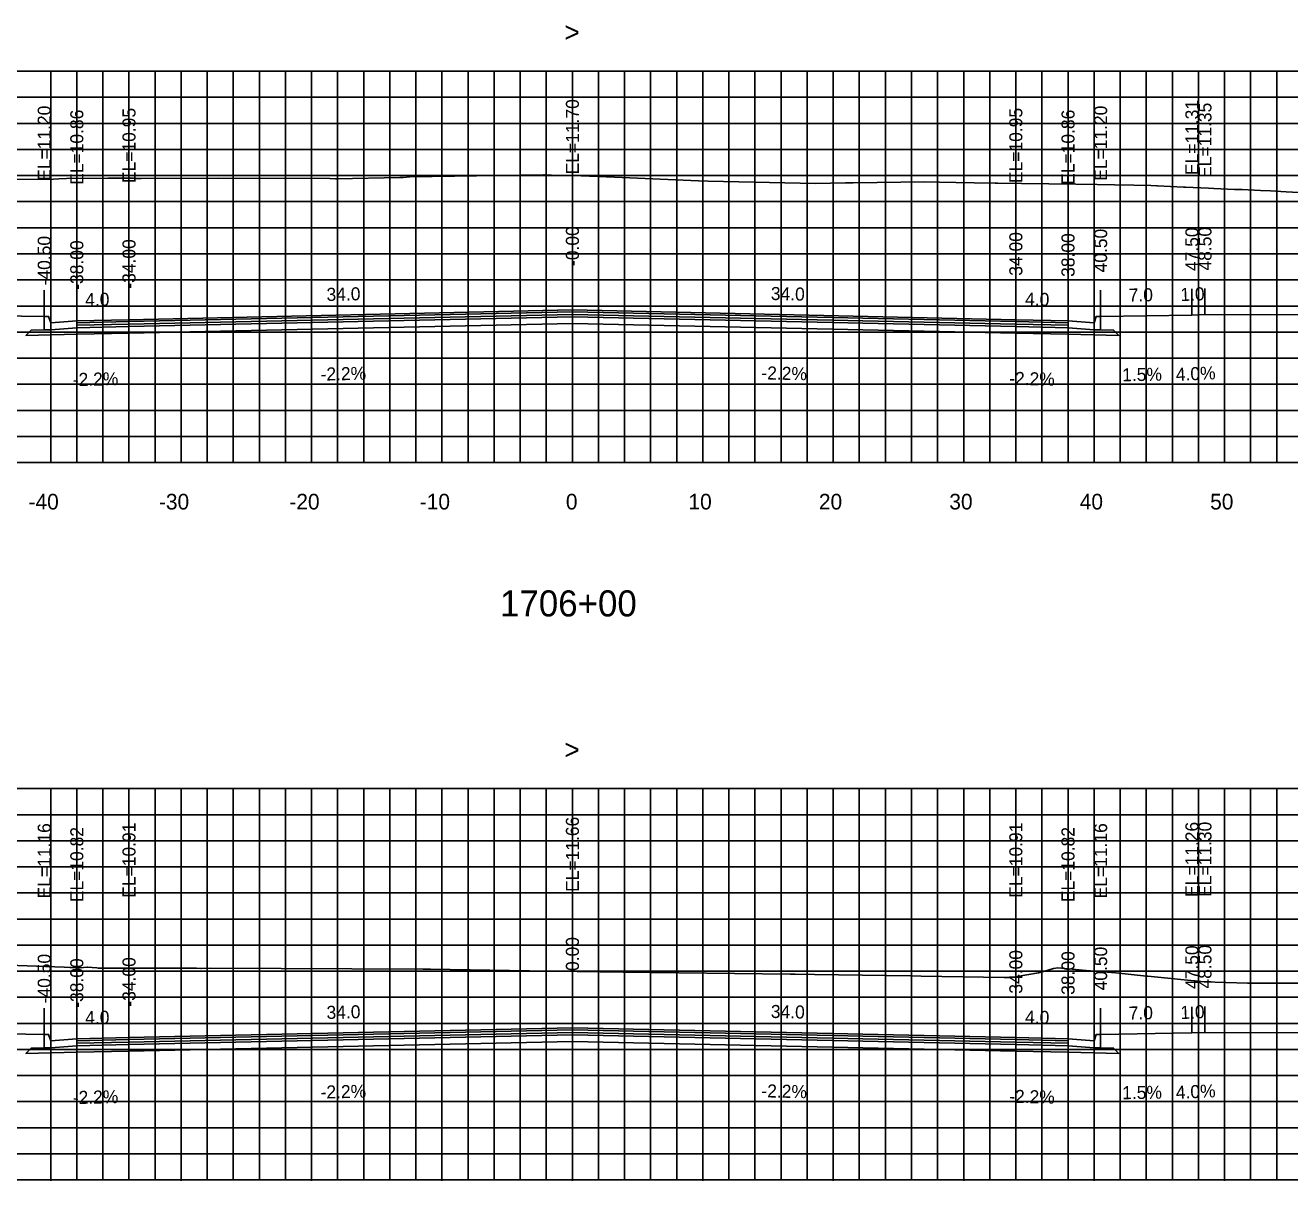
# Model space of a CAD drawing. Extents: x 1797789 to 1803805, y 249066 to 250293.
# Drawn here: x 1802929.1 to 1803026, y 250164.4 to 250253 of the extents above; entities that cross this region are included whole.
import ezdxf

# ---------------------------------------------------------------- set-up
doc = ezdxf.new("R2010")
doc.units = 0
for name, color, linetype in [('1', 7, 'Continuous'), ('10', 7, 'Continuous'), ('3', 7, 'Continuous'), ('4', 7, 'Continuous'), ('60', 7, 'Continuous'), ('BASE', 7, 'Continuous'), ('CL-CNST', 7, 'Continuous'), ('Level 62', 7, 'Continuous'), ('LOWER BINDER', 7, 'Continuous'), ('M-ROADS', 7, 'Continuous'), ('UPPER BINDER', 7, 'Continuous'), ('WEARING', 7, 'Continuous')]:
    doc.layers.add(name, color=color, linetype=linetype)

msp = doc.modelspace()

# ---------------------------------------------------------------- linework, layer by layer
for p, q in [((1802930.502, 250230.635), (1802930.502, 250232.635)), ((1802930.505, 250230.635), (1802930.505, 250232.635)), ((1802971.002, 250231.131), (1802971.002, 250233.131)), ((1803011.498, 250230.635), (1803011.498, 250232.635)), ((1803011.502, 250230.635), (1803011.502, 250232.635)), ((1803018.502, 250230.74), (1803018.502, 250232.74)), ((1803019.502, 250230.78), (1803019.502, 250232.78)), ((1802933.002, 250230.295), (1802933.002, 250232.295)), ((1802937.002, 250230.383), (1802937.002, 250232.383)), ((1803005.002, 250230.383), (1803005.002, 250232.383)), ((1803009.002, 250230.295), (1803009.002, 250232.295)), ((1802930.502, 250175.592), (1802930.502, 250177.592)), ((1802930.505, 250175.591), (1802930.505, 250177.591)), ((1802933.002, 250175.251), (1802933.002, 250177.251)), ((1802937.002, 250175.339), (1802937.002, 250177.339)), ((1802971.002, 250176.087), (1802971.002, 250178.087)), ((1803005.002, 250175.339), (1803005.002, 250177.339)), ((1803009.002, 250175.251), (1803009.002, 250177.251)), ((1803011.498, 250175.591), (1803011.498, 250177.591)), ((1803011.502, 250175.592), (1803011.502, 250177.592)), ((1803018.502, 250175.697), (1803018.502, 250177.697)), ((1803019.502, 250175.737), (1803019.502, 250177.737))]:
    msp.add_line(p, q)
for points in [[(1802933.002, 250230.295), (1802931.002, 250230.135), (1802930.835, 250230.635), (1802930.505, 250230.635), (1802930.505, 250229.605), (1802931.002, 250229.605), (1802933.002, 250229.765)], [(1803009.002, 250230.295), (1803011.002, 250230.135), (1803011.168, 250230.635), (1803011.498, 250230.635), (1803011.498, 250229.605), (1803011.002, 250229.605), (1803009.002, 250229.765)], [(1802933.002, 250175.251), (1802931.002, 250175.091), (1802930.835, 250175.591), (1802930.505, 250175.591), (1802930.505, 250174.561), (1802931.002, 250174.561), (1802933.002, 250174.721)], [(1803009.002, 250175.251), (1803011.002, 250175.091), (1803011.168, 250175.591), (1803011.498, 250175.591), (1803011.498, 250174.561), (1803011.002, 250174.561), (1803009.002, 250174.721)]]:
    msp.add_lwpolyline(points, close=True)
at = {"layer": '60'}
for p, q in [((1802821.002, 250219.432), (1803121.002, 250219.432)), ((1802931.002, 250219.372), (1802931.002, 250219.432)), ((1802941.002, 250219.372), (1802941.002, 250219.432)), ((1802951.002, 250219.372), (1802951.002, 250219.432)), ((1802961.002, 250219.372), (1802961.002, 250219.432)), ((1802971.002, 250219.372), (1802971.002, 250219.432)), ((1802981.002, 250219.372), (1802981.002, 250219.432)), ((1802991.002, 250219.372), (1802991.002, 250219.432)), ((1803001.002, 250219.372), (1803001.002, 250219.432)), ((1803011.002, 250219.372), (1803011.002, 250219.432)), ((1803021.002, 250219.372), (1803021.002, 250219.432)), ((1802821.002, 250164.432), (1803121.002, 250164.432)), ((1802931.002, 250164.372), (1802931.002, 250164.432)), ((1802941.002, 250164.372), (1802941.002, 250164.432)), ((1802951.002, 250164.372), (1802951.002, 250164.432)), ((1802961.002, 250164.372), (1802961.002, 250164.432)), ((1802971.002, 250164.372), (1802971.002, 250164.432)), ((1802981.002, 250164.372), (1802981.002, 250164.432)), ((1802991.002, 250164.372), (1802991.002, 250164.432)), ((1803001.002, 250164.372), (1803001.002, 250164.432)), ((1803011.002, 250164.372), (1803011.002, 250164.432)), ((1803021.002, 250164.372), (1803021.002, 250164.432))]:
    msp.add_line(p, q, dxfattribs=at)
at = {"layer": 'BASE'}
for points in [[(1803009.002, 250229.265), (1803012.902, 250229.179), (1803012.498, 250229.583), (1803011.498, 250229.605), (1803011.002, 250229.605), (1803009.002, 250229.765), (1803005.002, 250229.853), (1802971.002, 250230.601), (1802937.002, 250229.853), (1802933.002, 250229.765), (1802931.002, 250229.605), (1802930.505, 250229.605), (1802929.505, 250229.583), (1802929.101, 250229.179), (1802933.002, 250229.265), (1802937.002, 250229.353), (1802971.002, 250230.101), (1803005.002, 250229.353)], [(1803009.002, 250174.221), (1803012.902, 250174.136), (1803012.498, 250174.539), (1803011.498, 250174.561), (1803011.002, 250174.561), (1803009.002, 250174.721), (1803005.002, 250174.809), (1802971.002, 250175.557), (1802937.002, 250174.809), (1802933.002, 250174.721), (1802931.002, 250174.561), (1802930.505, 250174.561), (1802929.505, 250174.539), (1802929.101, 250174.136), (1802933.002, 250174.221), (1802937.002, 250174.309), (1802971.002, 250175.057), (1803005.002, 250174.309)]]:
    msp.add_lwpolyline(points, close=True, dxfattribs=at)
at = {"layer": 'CL-CNST'}
for points in [[(1802821.002, 250232.81), (1802922.502, 250230.78), (1802923.502, 250230.74), (1802930.502, 250230.635), (1802930.505, 250230.635), (1802930.835, 250230.635), (1802931.002, 250230.135), (1802933.002, 250230.295), (1802937.002, 250230.383), (1802971.002, 250231.131), (1803005.002, 250230.383), (1803009.002, 250230.295), (1803011.002, 250230.135), (1803011.168, 250230.635), (1803011.498, 250230.635), (1803011.502, 250230.635), (1803018.502, 250230.74), (1803019.502, 250230.78), (1803121.002, 250230.709)], [(1802821.002, 250179.096), (1802922.502, 250175.737), (1802923.502, 250175.697), (1802930.502, 250175.592), (1802930.505, 250175.591), (1802930.835, 250175.591), (1802931.002, 250175.091), (1802933.002, 250175.251), (1802937.002, 250175.339), (1802971.002, 250176.087), (1803005.002, 250175.339), (1803009.002, 250175.251), (1803011.002, 250175.091), (1803011.168, 250175.591), (1803011.498, 250175.591), (1803011.502, 250175.592), (1803018.502, 250175.697), (1803019.502, 250175.737), (1803121.002, 250175.671)]]:
    msp.add_lwpolyline(points, dxfattribs=at)
at = {"layer": 'Level 62'}
for p, q in [((1802821.002, 250249.432), (1803121.002, 250249.432)), ((1802931.002, 250219.432), (1802931.002, 250249.432)), ((1802933.002, 250219.432), (1802933.002, 250249.432)), ((1802935.002, 250219.432), (1802935.002, 250249.432)), ((1802937.002, 250219.432), (1802937.002, 250249.432)), ((1802939.002, 250219.432), (1802939.002, 250249.432)), ((1802941.002, 250219.432), (1802941.002, 250249.432)), ((1802943.002, 250219.432), (1802943.002, 250249.432)), ((1802945.002, 250219.432), (1802945.002, 250249.432)), ((1802947.002, 250219.432), (1802947.002, 250249.432)), ((1802949.002, 250219.432), (1802949.002, 250249.432)), ((1802951.002, 250219.432), (1802951.002, 250249.432)), ((1802953.002, 250219.432), (1802953.002, 250249.432)), ((1802955.002, 250219.432), (1802955.002, 250249.432)), ((1802957.002, 250219.432), (1802957.002, 250249.432)), ((1802959.002, 250219.432), (1802959.002, 250249.432)), ((1802961.002, 250219.432), (1802961.002, 250249.432)), ((1802963.002, 250219.432), (1802963.002, 250249.432)), ((1802965.002, 250219.432), (1802965.002, 250249.432)), ((1802967.002, 250219.432), (1802967.002, 250249.432)), ((1802969.002, 250219.432), (1802969.002, 250249.432)), ((1802971.002, 250219.432), (1802971.002, 250249.432)), ((1802973.002, 250219.432), (1802973.002, 250249.432)), ((1802975.002, 250219.432), (1802975.002, 250249.432)), ((1802977.002, 250219.432), (1802977.002, 250249.432)), ((1802979.002, 250219.432), (1802979.002, 250249.432)), ((1802981.002, 250219.432), (1802981.002, 250249.432)), ((1802983.002, 250219.432), (1802983.002, 250249.432)), ((1802985.002, 250219.432), (1802985.002, 250249.432)), ((1802987.002, 250219.432), (1802987.002, 250249.432)), ((1802989.002, 250219.432), (1802989.002, 250249.432)), ((1802991.002, 250219.432), (1802991.002, 250249.432)), ((1802993.002, 250219.432), (1802993.002, 250249.432)), ((1802995.002, 250219.432), (1802995.002, 250249.432)), ((1802997.002, 250219.432), (1802997.002, 250249.432)), ((1802999.002, 250219.432), (1802999.002, 250249.432)), ((1803001.002, 250219.432), (1803001.002, 250249.432)), ((1803003.002, 250219.432), (1803003.002, 250249.432)), ((1803005.002, 250219.432), (1803005.002, 250249.432)), ((1803007.002, 250219.432), (1803007.002, 250249.432)), ((1803009.002, 250219.432), (1803009.002, 250249.432)), ((1803011.002, 250219.432), (1803011.002, 250249.432)), ((1803013.002, 250219.432), (1803013.002, 250249.432)), ((1803015.002, 250219.432), (1803015.002, 250249.432)), ((1803017.002, 250219.432), (1803017.002, 250249.432)), ((1803019.002, 250219.432), (1803019.002, 250249.432)), ((1803021.002, 250219.432), (1803021.002, 250249.432)), ((1803023.002, 250219.432), (1803023.002, 250249.432)), ((1803025.002, 250219.432), (1803025.002, 250249.432)), ((1802821.002, 250247.432), (1803121.002, 250247.432)), ((1802821.002, 250245.432), (1803121.002, 250245.432)), ((1802821.002, 250243.432), (1803121.002, 250243.432)), ((1802821.002, 250241.432), (1803121.002, 250241.432)), ((1802821.002, 250239.432), (1803121.002, 250239.432)), ((1802821.002, 250237.432), (1803121.002, 250237.432)), ((1802821.002, 250235.432), (1803121.002, 250235.432)), ((1802821.002, 250233.432), (1803121.002, 250233.432)), ((1802821.002, 250231.432), (1803121.002, 250231.432)), ((1802821.002, 250229.432), (1803121.002, 250229.432)), ((1802821.002, 250227.432), (1803121.002, 250227.432)), ((1802821.002, 250225.432), (1803121.002, 250225.432)), ((1802821.002, 250223.432), (1803121.002, 250223.432)), ((1802821.002, 250221.432), (1803121.002, 250221.432)), ((1802821.002, 250219.432), (1803121.002, 250219.432)), ((1802821.002, 250194.432), (1803121.002, 250194.432)), ((1802931.002, 250164.432), (1802931.002, 250194.432)), ((1802933.002, 250164.432), (1802933.002, 250194.432)), ((1802935.002, 250164.432), (1802935.002, 250194.432)), ((1802937.002, 250164.432), (1802937.002, 250194.432)), ((1802939.002, 250164.432), (1802939.002, 250194.432)), ((1802941.002, 250164.432), (1802941.002, 250194.432)), ((1802943.002, 250164.432), (1802943.002, 250194.432)), ((1802945.002, 250164.432), (1802945.002, 250194.432)), ((1802947.002, 250164.432), (1802947.002, 250194.432)), ((1802949.002, 250164.432), (1802949.002, 250194.432)), ((1802951.002, 250164.432), (1802951.002, 250194.432)), ((1802953.002, 250164.432), (1802953.002, 250194.432)), ((1802955.002, 250164.432), (1802955.002, 250194.432)), ((1802957.002, 250164.432), (1802957.002, 250194.432)), ((1802959.002, 250164.432), (1802959.002, 250194.432)), ((1802961.002, 250164.432), (1802961.002, 250194.432)), ((1802963.002, 250164.432), (1802963.002, 250194.432)), ((1802965.002, 250164.432), (1802965.002, 250194.432)), ((1802967.002, 250164.432), (1802967.002, 250194.432)), ((1802969.002, 250164.432), (1802969.002, 250194.432)), ((1802971.002, 250164.432), (1802971.002, 250194.432)), ((1802973.002, 250164.432), (1802973.002, 250194.432)), ((1802975.002, 250164.432), (1802975.002, 250194.432)), ((1802977.002, 250164.432), (1802977.002, 250194.432)), ((1802979.002, 250164.432), (1802979.002, 250194.432)), ((1802981.002, 250164.432), (1802981.002, 250194.432)), ((1802983.002, 250164.432), (1802983.002, 250194.432)), ((1802985.002, 250164.432), (1802985.002, 250194.432)), ((1802987.002, 250164.432), (1802987.002, 250194.432)), ((1802989.002, 250164.432), (1802989.002, 250194.432)), ((1802991.002, 250164.432), (1802991.002, 250194.432)), ((1802993.002, 250164.432), (1802993.002, 250194.432)), ((1802995.002, 250164.432), (1802995.002, 250194.432)), ((1802997.002, 250164.432), (1802997.002, 250194.432)), ((1802999.002, 250164.432), (1802999.002, 250194.432)), ((1803001.002, 250164.432), (1803001.002, 250194.432)), ((1803003.002, 250164.432), (1803003.002, 250194.432)), ((1803005.002, 250164.432), (1803005.002, 250194.432)), ((1803007.002, 250164.432), (1803007.002, 250194.432)), ((1803009.002, 250164.432), (1803009.002, 250194.432)), ((1803011.002, 250164.432), (1803011.002, 250194.432)), ((1803013.002, 250164.432), (1803013.002, 250194.432)), ((1803015.002, 250164.432), (1803015.002, 250194.432)), ((1803017.002, 250164.432), (1803017.002, 250194.432)), ((1803019.002, 250164.432), (1803019.002, 250194.432)), ((1803021.002, 250164.432), (1803021.002, 250194.432)), ((1803023.002, 250164.432), (1803023.002, 250194.432)), ((1803025.002, 250164.432), (1803025.002, 250194.432)), ((1802821.002, 250192.432), (1803121.002, 250192.432)), ((1802821.002, 250190.432), (1803121.002, 250190.432)), ((1802821.002, 250188.432), (1803121.002, 250188.432)), ((1802821.002, 250186.432), (1803121.002, 250186.432)), ((1802821.002, 250184.432), (1803121.002, 250184.432)), ((1802821.002, 250182.432), (1803121.002, 250182.432)), ((1802821.002, 250180.432), (1803121.002, 250180.432)), ((1802821.002, 250178.432), (1803121.002, 250178.432)), ((1802821.002, 250176.432), (1803121.002, 250176.432)), ((1802821.002, 250174.432), (1803121.002, 250174.432)), ((1802821.002, 250172.432), (1803121.002, 250172.432)), ((1802821.002, 250170.432), (1803121.002, 250170.432)), ((1802821.002, 250168.432), (1803121.002, 250168.432)), ((1802821.002, 250166.432), (1803121.002, 250166.432)), ((1802821.002, 250164.432), (1803121.002, 250164.432))]:
    msp.add_line(p, q, dxfattribs=at)
at = {"layer": 'LOWER BINDER'}
for points in [[(1802933.002, 250229.765), (1802933.002, 250229.955), (1802937.002, 250230.043), (1802971.002, 250230.791), (1803005.002, 250230.043), (1803009.002, 250229.955), (1803009.002, 250229.765), (1803005.002, 250229.853), (1802971.002, 250230.601), (1802937.002, 250229.853)], [(1802933.002, 250174.721), (1802933.002, 250174.911), (1802937.002, 250174.999), (1802971.002, 250175.747), (1803005.002, 250174.999), (1803009.002, 250174.911), (1803009.002, 250174.721), (1803005.002, 250174.809), (1802971.002, 250175.557), (1802937.002, 250174.809)]]:
    msp.add_lwpolyline(points, close=True, dxfattribs=at)
at = {"layer": 'M-ROADS'}
for points in [[(1802923.411, 250241.142), (1802931.208, 250241.164), (1802931.613, 250241.183), (1802932.202, 250241.21), (1802935.375, 250241.225), (1802937.349, 250241.225), (1802937.466, 250241.219), (1802937.941, 250241.196), (1802943.875, 250241.242), (1802952.391, 250241.207), (1802952.849, 250241.189), (1802952.93, 250241.186), (1802957.764, 250241.279), (1802958.031, 250241.294), (1802958.528, 250241.323), (1802968.795, 250241.483), (1802968.867, 250241.48), (1802969.399, 250241.461), (1802969.967, 250241.433), (1802970.044, 250241.432), (1802970.129, 250241.431), (1802970.685, 250241.437), (1802970.849, 250241.435), (1802971.031, 250241.431), (1802974.229, 250241.316), (1802980.666, 250241.021), (1802981.415, 250241.014), (1802989.634, 250240.82), (1802991.94, 250240.868), (1802992.112, 250240.866), (1802992.525, 250240.863), (1802998.012, 250240.947), (1802999.137, 250240.928), (1803000.394, 250240.908), (1803001.809, 250240.886), (1803003.412, 250240.86), (1803003.61, 250240.862), (1803005.437, 250240.831), (1803007.532, 250240.797), (1803009.614, 250240.768), (1803011.233, 250240.746), (1803012.555, 250240.721), (1803014.053, 250240.692), (1803015.348, 250240.667), (1803015.807, 250240.646), (1803015.849, 250240.644), (1803015.862, 250240.643), (1803017.856, 250240.55), (1803018.02, 250240.544), (1803019.782, 250240.462), (1803020.191, 250240.448), (1803021.767, 250240.376), (1803022.225, 250240.361), (1803022.363, 250240.354), (1803023.751, 250240.292), (1803024.534, 250240.25), (1803025.732, 250240.196), (1803026.707, 250240.143)], [(1802926.336, 250180.937), (1802931.325, 250180.76), (1802932.029, 250180.744), (1802932.477, 250180.729), (1802932.577, 250180.725), (1802933.102, 250180.703), (1802933.112, 250180.703), (1802933.271, 250180.696), (1802933.765, 250180.735), (1802933.775, 250180.738), (1802933.832, 250180.734), (1802934.534, 250180.695), (1802934.537, 250180.695), (1802934.649, 250180.676), (1802934.673, 250180.675), (1802934.695, 250180.673), (1802934.719, 250180.674), (1802937.265, 250180.669), (1802938.277, 250180.662), (1802940, 250180.654), (1802942.17, 250180.654), (1802942.179, 250180.654), (1802942.513, 250180.647), (1802942.528, 250180.647), (1802943.222, 250180.656), (1802959.521, 250180.594), (1802959.804, 250180.59), (1802960.112, 250180.586), (1802969.231, 250180.424), (1802969.466, 250180.427), (1802969.603, 250180.429), (1802974.883, 250180.364), (1802987.699, 250180.196), (1802988.046, 250180.201), (1802988.087, 250180.201), (1802989.577, 250180.187), (1802996.93, 250180.07), (1802997.748, 250180.059), (1803004.116, 250179.956), (1803004.627, 250179.951), (1803004.7, 250179.95), (1803004.723, 250179.957), (1803004.938, 250179.99), (1803006.749, 250180.31), (1803007.226, 250180.445), (1803007.882, 250180.633), (1803008.217, 250180.682), (1803010.394, 250180.497), (1803012.672, 250180.307), (1803015.029, 250180.049), (1803015.113, 250180.052), (1803019.43, 250179.609), (1803022.776, 250179.522), (1803022.868, 250179.524), (1803023.148, 250179.521), (1803023.265, 250179.519), (1803029.36, 250179.504)]]:
    msp.add_lwpolyline(points, dxfattribs=at)
at = {"layer": 'UPPER BINDER'}
for points in [[(1802971.002, 250230.791), (1802937.002, 250230.043), (1802933.002, 250229.955), (1802933.002, 250230.145), (1802937.002, 250230.233), (1802971.002, 250230.981), (1803005.002, 250230.233), (1803009.002, 250230.145), (1803009.002, 250229.765), (1803009.002, 250229.955), (1803005.002, 250230.043)], [(1802971.002, 250175.747), (1802937.002, 250174.999), (1802933.002, 250174.911), (1802933.002, 250175.101), (1802937.002, 250175.189), (1802971.002, 250175.937), (1803005.002, 250175.189), (1803009.002, 250175.101), (1803009.002, 250174.721), (1803009.002, 250174.911), (1803005.002, 250174.999)]]:
    msp.add_lwpolyline(points, close=True, dxfattribs=at)
at = {"layer": 'WEARING'}
for points in [[(1803009.002, 250230.145), (1803009.002, 250230.295), (1803005.002, 250230.383), (1802971.002, 250231.131), (1802937.002, 250230.383), (1802933.002, 250230.295), (1802933.002, 250230.145), (1802937.002, 250230.233), (1802971.002, 250230.981), (1803005.002, 250230.233)], [(1803009.002, 250175.101), (1803009.002, 250175.251), (1803005.002, 250175.339), (1802971.002, 250176.087), (1802937.002, 250175.339), (1802933.002, 250175.251), (1802933.002, 250175.101), (1802937.002, 250175.189), (1802971.002, 250175.937), (1803005.002, 250175.189)]]:
    msp.add_lwpolyline(points, close=True, dxfattribs=at)

# ---------------------------------------------------------------- texts
at = {"layer": '1'}
msp.add_text('1706+00', height=2, dxfattribs=at).set_placement((1802965.452, 250207.632))
at = {"layer": '10'}
for s, p in [('-40', (1802929.298, 250215.832)), ('-30', (1802939.298, 250215.832)), ('-20', (1802949.298, 250215.832)), ('-10', (1802959.298, 250215.832)), ('0', (1802970.501, 250215.832)), ('10', (1802979.901, 250215.832)), ('20', (1802989.901, 250215.832)), ('30', (1802999.901, 250215.832)), ('40', (1803009.901, 250215.832)), ('50', (1803019.901, 250215.832))]:
    msp.add_text(s, height=1.2, dxfattribs=at).set_placement(p)
at = {"layer": '3'}
for s, p in [('EL=11.70', (1802971.502, 250241.525)), ('EL=11.31', (1803019.002, 250241.465)), ('EL=11.20', (1802931.002, 250241.029)), ('EL=11.20', (1802931.005, 250241.029)), ('EL=10.86', (1802933.502, 250240.72)), ('EL=10.95', (1802937.502, 250240.855)), ('EL=10.95', (1803005.502, 250240.855)), ('EL=10.86', (1803009.502, 250240.72)), ('EL=11.20', (1803011.998, 250241.029)), ('EL=11.20', (1803012.002, 250241.029)), ('EL=11.35', (1803020.002, 250241.253)), ('-0.00', (1802971.502, 250234.501)), ('40.50', (1803011.998, 250234.005)), ('40.50', (1803012.002, 250234.005)), ('47.50', (1803019.002, 250234.11)), ('48.50', (1803020.002, 250234.15)), ('-40.50', (1802931.002, 250233.013)), ('-40.50', (1802931.005, 250233.013)), ('-38.00', (1802933.502, 250232.673)), ('-34.00', (1802937.502, 250232.761)), ('34.00', (1803005.502, 250233.753)), ('38.00', (1803009.502, 250233.665)), ('EL=10.91', (1802937.502, 250186.064)), ('EL=11.66', (1802971.502, 250186.513)), ('EL=10.91', (1803005.502, 250186.064)), ('EL=11.26', (1803019.002, 250186.122)), ('EL=11.30', (1803020.002, 250186.13)), ('EL=11.16', (1802931.002, 250186.017)), ('EL=11.16', (1802931.005, 250186.017)), ('EL=10.82', (1802933.502, 250185.724)), ('EL=10.82', (1803009.502, 250185.724)), ('EL=11.16', (1803011.998, 250186.017)), ('EL=11.16', (1803012.002, 250186.017)), ('0.00', (1802971.502, 250180.45)), ('40.50', (1803011.998, 250178.962)), ('40.50', (1803012.002, 250178.962)), ('47.50', (1803019.002, 250179.067)), ('48.50', (1803020.002, 250179.107)), ('-40.50', (1802931.002, 250177.97)), ('-40.50', (1802931.005, 250177.969)), ('-38.00', (1802933.502, 250177.629)), ('-34.00', (1802937.502, 250177.717)), ('34.00', (1803005.502, 250178.71)), ('38.00', (1803009.502, 250178.622))]:
    msp.add_text(s, height=1, rotation=90, dxfattribs=at).set_placement(p)
at = {"layer": '4'}
for s, rotation, p in [('4.0', 1.2603, (1802933.655, 250231.41)), ('34.0', 1.2603, (1802952.159, 250231.817)), ('34.0', 358.7397, (1802986.207, 250231.897)), ('4.0', 358.7397, (1803005.703, 250231.468)), ('7.0', 0.85937, (1803013.662, 250231.768)), ('1.0', 2.29061, (1803017.636, 250231.806)), ('-2.2%', 1.2603, (1802951.703, 250225.705)), ('-2.2%', 358.7397, (1802985.483, 250225.811)), ('1.5%', 0.85937, (1803013.163, 250225.66)), ('4.0%', 2.29061, (1803017.29, 250225.688)), ('-2.2%', 1.2603, (1802932.703, 250225.287)), ('-2.2%', 358.7397, (1803004.483, 250225.393)), ('4.0', 1.2603, (1802933.655, 250176.366)), ('34.0', 1.2603, (1802952.159, 250176.773)), ('34.0', 358.7397, (1802986.207, 250176.853)), ('4.0', 358.7397, (1803005.703, 250176.424)), ('7.0', 0.85937, (1803013.662, 250176.724)), ('1.0', 2.29061, (1803017.636, 250176.763)), ('-2.2%', 1.2603, (1802951.703, 250170.662)), ('-2.2%', 358.7397, (1802985.483, 250170.768)), ('1.5%', 0.85937, (1803013.163, 250170.616)), ('4.0%', 2.29061, (1803017.29, 250170.644)), ('-2.2%', 1.2603, (1802932.703, 250170.244)), ('-2.2%', 358.7397, (1803004.483, 250170.35))]:
    msp.add_text(s, height=1, rotation=rotation, dxfattribs=at).set_placement(p)
at = {"layer": '60'}
for p in [(1802970.393, 250251.682), (1802970.393, 250196.682)]:
    msp.add_text('>', height=1.5, dxfattribs=at).set_placement(p)

doc.saveas('drawing.dxf')
